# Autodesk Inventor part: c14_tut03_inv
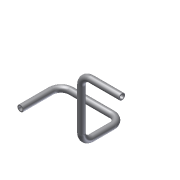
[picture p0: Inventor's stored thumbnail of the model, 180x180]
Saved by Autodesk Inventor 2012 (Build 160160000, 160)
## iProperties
Created: 2010-04
Part Number: c14_tut03_inv
Document SubType Name: Modeling
Designer: CADSoft
Density: 1 g/cm^3
Material: Default
Author: CADSoft
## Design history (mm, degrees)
sketch "Sketch1"
  geometry: L1 (0, 0)-(0, 40); L2 (0, 40)-(60, 40); L3 (60, 40)-(60, 0)
  constraints: 6 end point, 2 perpendicular, 1 vertical
  dimensions: "d0" = 40 distance of L1.start L1.end; "d2" = 60 distance of L1.end L2.end; "d4" = 40 distance of L2.end L3.end
workplane "Work Plane1"
sketch "Sketch2"
  geometry: L1 (0, 0)-(0, 60); L2 (0, 0)-(60, 0); L3 (0, 60)-(40, 60); 1 further point
  constraints: 6 end point, 2 perpendicular, 1 horizontal, 1 vertical
  dimensions: "d5" = 60 distance of L1.start L1.end; "d6" = 90 deg angle of L2 L1 (derived); "d7" = 40 distance of L1.end L3.end; "d8" = 90 deg angle of L1 L3 (derived)
sketch "3D Sketch1" dims "d9" = 10, "d11" = 10 (= d9)
  geometry: L1 through (10, 10) direction (-1, 0); L2 through (0, 50) direction (0, 1); 15 other entities
  constraints: 2 horizontal, 2 vertical
  dimensions: "d10" = 10 distance of the line from the sketch origin of L1 (= d9); "d12" = 10 dimension on L2 (= d9)
workplane "Work Plane2"
sketch "Sketch3"
  geometry: C1 r 3 at (0, 0); C2 r 2 at (0, 0); 1 further point
  constraints: 2 centre point, 2 coincident
  dimensions: "d13" = 4 diameter of C2; "d14" = 6 diameter of C1
sweep "Sweep1" sketch "Sketch3" dims "d15" = 0
body "Solid1"
